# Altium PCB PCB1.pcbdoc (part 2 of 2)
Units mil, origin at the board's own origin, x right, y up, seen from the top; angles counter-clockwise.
Board outline 3622 x 3621.7 mil, 4 copper layers (Top Layer, Inner1, Inner2, Bottom Layer), stack 62.5 mil thick; 107 components, 108 nets, 595 pads, 260 vias.
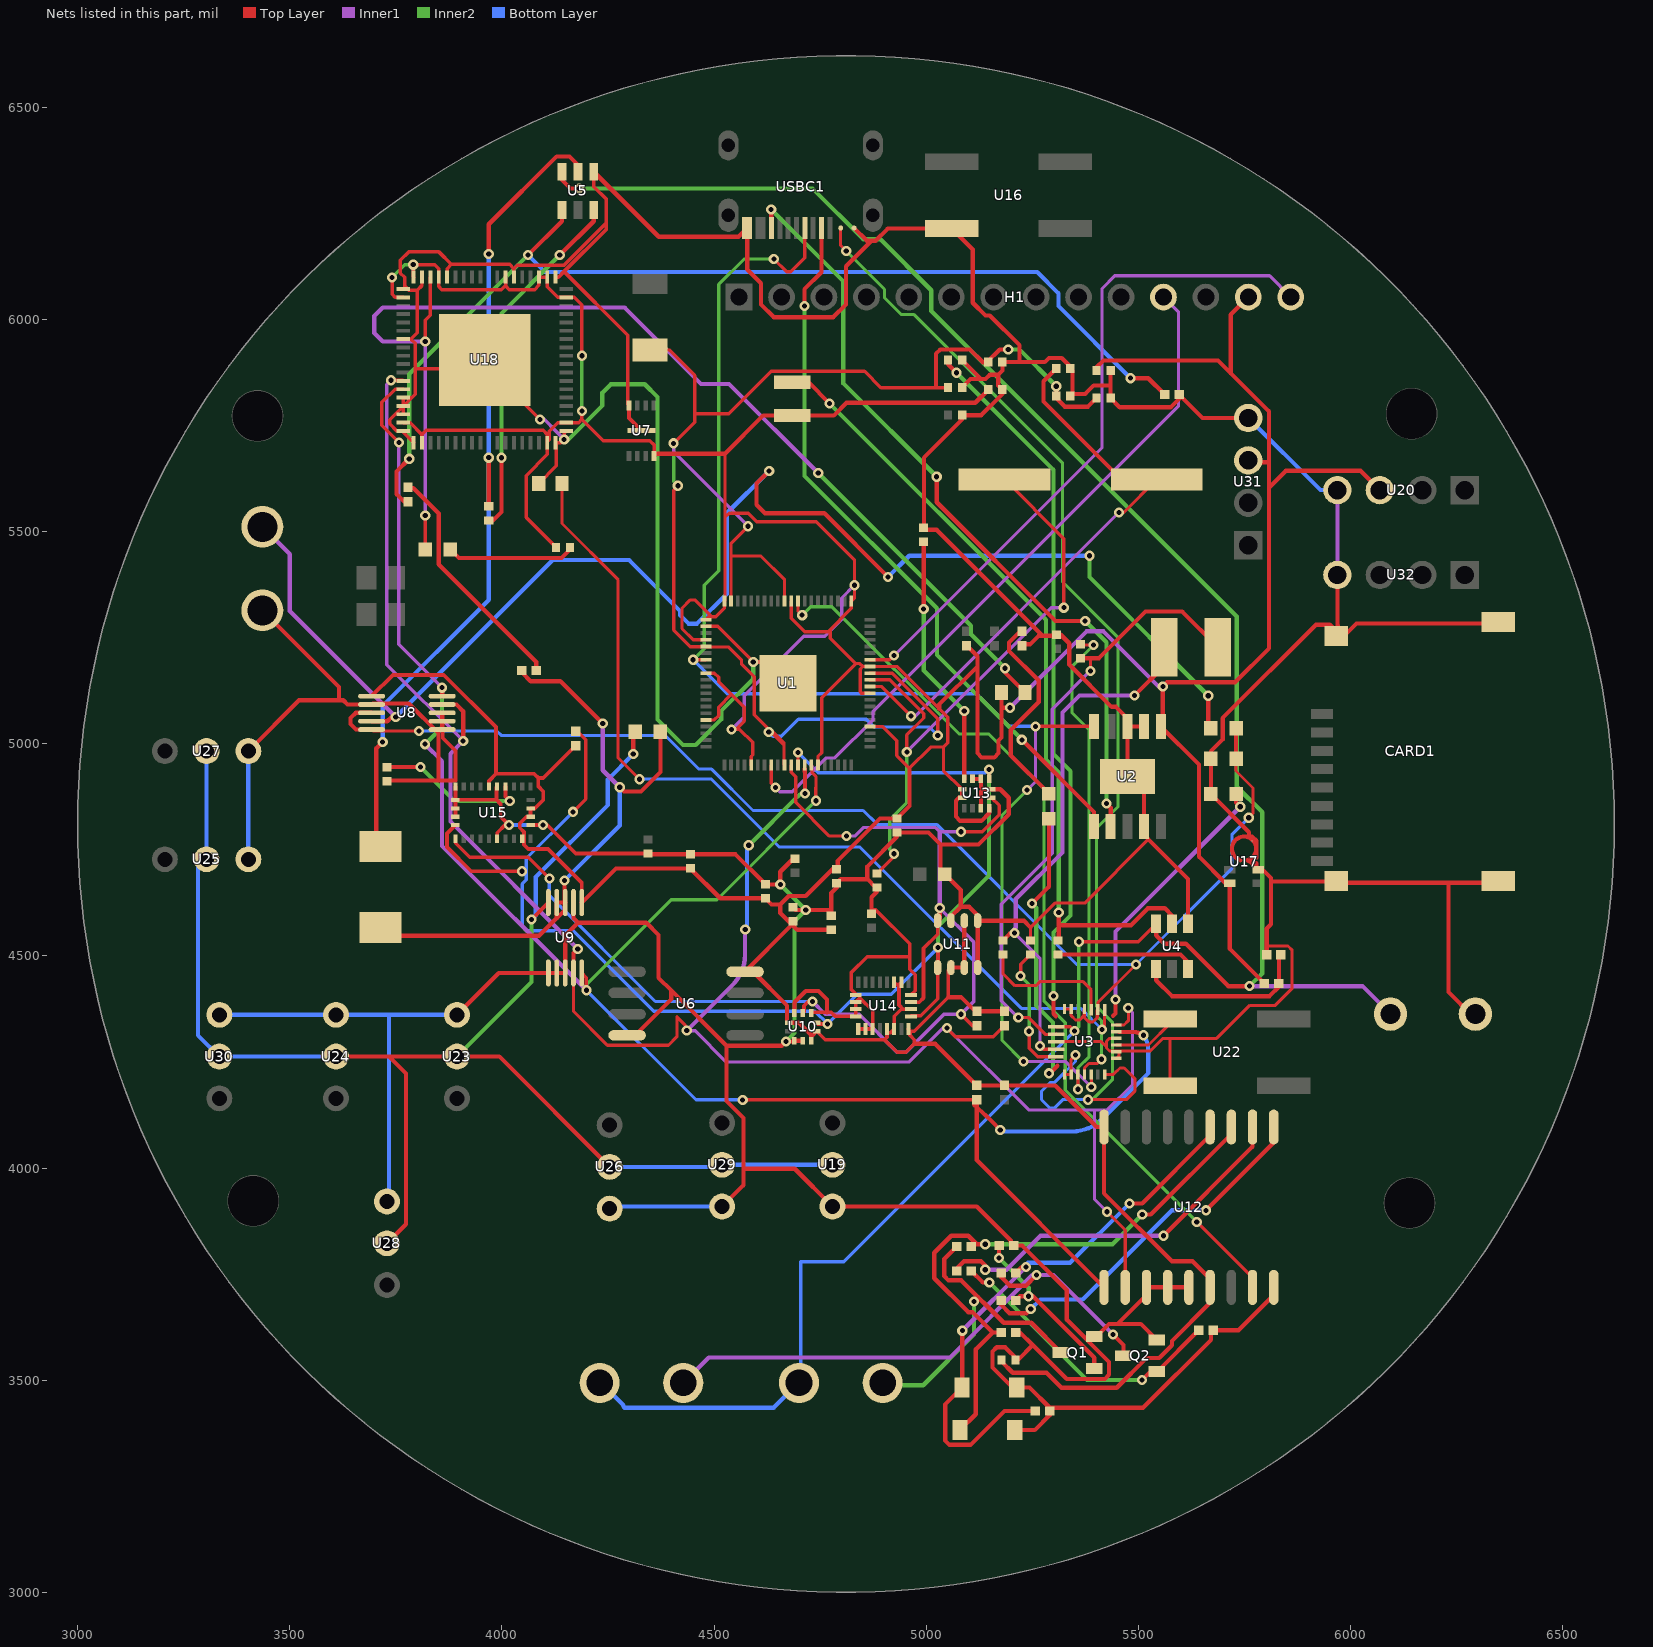
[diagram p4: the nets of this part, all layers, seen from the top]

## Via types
v1: diameter 24, hole 12, Top Layer to Bottom Layer, tented both sides, 260 vias

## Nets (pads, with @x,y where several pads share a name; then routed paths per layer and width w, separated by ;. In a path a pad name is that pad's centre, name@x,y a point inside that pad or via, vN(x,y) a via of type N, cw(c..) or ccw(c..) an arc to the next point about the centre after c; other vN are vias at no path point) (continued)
$1N198: R36.1 U1.11 U10.4 U11.5 U13.11 U14.4 U15.20 | length 2975.9
  Top Layer w7.8: U15.20@3890.5,4776.4 3890.5,4766.4 3924.2,4732.7 4062,4732.7 v1(4112,4682.7) ; U1.11@4682,4949.7 4682,4932.7 4692.4,4922.3 4692.4,4862.3 4772,4782.7 v1(4812,4782.7) ; v1(5082,4792.7) 5132,4792.7 5172,4832.7 5172,4854.7 U13.11@5153.6,4873.1
  Top Layer w8.5: U10.4@4709.1,4365.5 4712,4368.4 4712,4382.7 4722,4392.7 v1(4732,4392.7) ; U14.4@4964.1,4391.4 4964.4,4391.1 4983.7,4391.1 4993.7,4401.1 4993.7,4517.9 5026.9,4551.1 U11.5@5026.9,4583.1 ; v1(5082,4362.7) 5108.9,4335.8 R36.1@5119.3,4335.8
  Top Layer w9.9: U11.5@5026.9,4583.1 5032,4588.2 v1(5032,4612.7)
  Inner1 w7.8: v1(4812,4782.7) 4832,4782.7 4852,4802.7 5022,4802.7 5032,4792.7 v1(5082,4792.7)
  Inner1 w8.5: v1(4732,4392.7) 4762,4362.7 4842,4362.7 4932,4272.7 4952,4272.7 5042,4362.7 v1(5082,4362.7) 5112,4392.7 5112,4532.7 v1(5032,4612.7)
  Inner1 w9.9: v1(5032,4612.7) 5032,4792.7
  Bottom Layer w7.8: v1(4112,4682.7) 4112,4642.7 4362,4392.7 v1(4732,4392.7)
$1N204: C25.1 U15.9 | length 361.4
  Top Layer w8.9: C25.1@3729.1,4944.5 3729.8,4945.2 v1(3808.6,4945.2) ; U15.9@4008.6,4899.5 4008.6,4875.2 v1(4018.6,4865.2)
  Inner2 w8.9: v1(3808.6,4945.2) 3888.6,4865.2 v1(4018.6,4865.2)
$1N209: LED2.2 U3.1 | length 669
  Top Layer w10: v1(5249.1,4623.4) 5289.1,4663.4 LED2.2@5289.1,4823.4 ; v1(5289.1,4223.4) 5291.4,4223.4 5309.3,4241.3
  Inner2 w10: v1(5249.1,4623.4) 5259.1,4613.4 5259.1,4383.4 5299.1,4343.4 5299.1,4233.4 v1(5289.1,4223.4)
$1N210: LED2.1 R8.1 | length 491.1
  Top Layer w10: R8.1@5225.4,5265.5 5222.1,5265.5 5195.4,5238.8 5195.4,5218.8 5265.4,5148.8 5265.4,5098.8 5199.1,5032.5 5199.1,4972.5 LED2.1@5289.1,4882.5
$1N211: C17.1 U3.4 | length 1161.3
  Top Layer w7.1: v1(5357.4,4185.8) U3.4@5357.4,4221.2 ; C17.1@5364.1,5234.5 5366.1,5232.5 v1(5394.1,5232.5)
  Inner2 w7.1: v1(5357.4,4185.8) 5357.4,4235.8 5384.1,4262.5 5384.1,5032.5 5344.1,5072.5 5344.1,5182.5 v1(5394.1,5232.5)
$1N212: C17.2 L4.1 U3.26 | length 1460.1
  Top Layer w7.8: v1(5217.1,4354.8) 5242.1,4354.8 5282.1,4314.8 5305.3,4314.8 U3.26@5306.2,4315.7 ; v1(5387.1,5171.8) 5387.1,5201.8
  Top Layer w10: C17.2@5364.1,5201.4 5364.5,5201.8 5407.1,5201.8 5517.1,5311.8 5603.2,5311.8 L4.1@5687.1,5227.9
  Inner1 w7.8: v1(5217.1,4354.8) 5177.1,4394.8 5177.1,4621.8 5297.1,4741.8 5297.1,5081.8 v1(5387.1,5171.8)
$1N215: U3.12 U22.1 | length 158.8
  Top Layer w7.1: U3.12@5447.9,4290.1 5523.9,4290.1 5575.2,4341.4 U22.1@5575.2,4351.7
$1N219: C18.1 U3.19 | length 324.6
  Top Layer w7.1: C18.1@5180.9,4503.6 5180.9,4458 5208.9,4430.1 5258.9,4430.1 5268.9,4440.1 5368.9,4440.1 5388.9,4420.1 U3.19@5388.9,4373.1
$1N221: R1.1 U3.16 | length 651
  Top Layer w10: 5440.5,4359 5446,4364.5 U3.16@5446,4368.8 v1(5446,4397.4) ; R1.1@5730.2,4881.7 5730.2,4861.7 v1(5740.2,4851.7)
  Inner1 w10: v1(5446,4397.4) 5446,4557.4 v1(5740.2,4851.7)
$1N224: C10.1 U3.25 U4.3 U5.3 U21.1 U33.1 | length 5744.7
  Top Layer w7.8: U3.25@5306.2,4333.4 5339.8,4333.4 v1(5349.8,4323.4) ; v1(5359.8,4533.4) 5499.7,4533.4 U4.3@5541.9,4575.6
  Top Layer w10: U5.3@4141.9,6347.9 4141.9,6328.9 4161.9,6308.9 v1(4181.9,6308.9) ; U4.3@5541.9,4575.6 5541.9,4548.9 5561.9,4528.9 5611.9,4528.9 5711.9,4428.9 v1(5761.9,4428.9)
  Inner1 w10: v1(5761.9,4428.9) 6028.1,4428.9 C10.1@6094.1,4362.9
  Inner2 w7.8: v1(5349.8,4323.4) 5359.8,4333.4 v1(5359.8,4533.4)
  Inner2 w10: v1(4181.9,6308.9) 4731.9,6308.9 4851.9,6188.9 4891.9,6188.9 5011.9,6068.9 5011.9,6020.1 5731.9,5300.1 5731.9,4898.9 5791.9,4838.9 5791.9,4458.9 v1(5761.9,4428.9)
  Bottom Layer w7.8: U21.1@4700.5,3493.9 4700.5,3495.2 4704.6,3499.3 4704.6,3779.3 ; 4706,3779.5 4805.9,3779.5 v1(5349.8,4323.4)
  Bottom Layer w10: U33.1@4244.8,3483.3 4283.7,3444.4 ; 4283.63,3444.33 cw(c4276.7,3437.4) 4286.5,3437.4 ; 4289.2,3435.2 4640.5,3435.2 U21.1@4700.5,3495.2
$1N225: C19.1 U3.29 | length 309.9
  Top Layer w7.8: v1(5222.6,4452.5) 5222.6,4480.2 C19.1@5245.9,4503.6 ; v1(5242.6,4322.5) 5242.6,4282.5 5262.6,4262.5 U3.29@5305.2,4262.5
  Inner2 w7.8: v1(5222.6,4452.5) 5242.6,4432.5 v1(5242.6,4322.5)
$1N229: C18.2 L4.2 U3.28 | length 1262.7
  Top Layer w7.8: v1(5268.3,4288.1) 5276.2,4280.2 U3.28@5306.2,4280.2
  Top Layer w10: C18.2@5180.9,4536.6 5198.3,4554 v1(5208.3,4554) ; v1(5491.1,5114) 5561.1,5184 L4.2@5561.1,5227.9
  Inner1 w7.8: v1(5208.3,4554) 5268.3,4494 v1(5268.3,4288.1)
  Inner1 w10: v1(5208.3,4554) 5208.3,4564 5211.1,4566.8 5211.1,4634 5321.1,4744 5321.1,5074 5361.1,5114 v1(5491.1,5114)
$1N233: U2.7 USBC1.B5 | length 1870.9
  Top Layer w10: v1(4634.7,6259.3) 4634.7,6216 USBC1.B5@4635.2,6215.5 ; v1(5024.7,5629.3) 5024.7,5569.3 5304.7,5289.3 v1(5374.7,5289.3) ; v1(5424.7,4859.3) 5434.7,4849.3 U2.7@5434.7,4804.8
  Inner2 w10: v1(4634.7,6259.3) 4804.7,6089.3 4804.7,5849.3 v1(5024.7,5629.3) ; v1(5374.7,5289.3) 5424.7,5239.3 v1(5424.7,4859.3)
$1N234: U2.6 USBC1.A5 | length 1709.8
  Top Layer w10: v1(4713.3,6031.4) 4713.3,6071.4 4753.3,6111.4 USBC1.A5@4753.3,6215.5 ; v1(5225.4,5009.4) 5395.4,4839.4 U2.6@5395.4,4804.8
  Inner2 w10: v1(4713.3,6031.4) 4713.3,5631.4 5025.4,5319.3 5025.4,5209.4 v1(5225.4,5009.4)
$1N235: U1.67 U2.5 U3.6 USBC1.A6 | length 3331
  Top Layer w7.1: v1(5389,4191) U3.6@5389,4221
  Top Layer w7.8: v1(4450.9,5198.1) U1.67@4480.9,5198.1 ; v1(4640.9,6142.5) 4670.9,6112.5 4680.9,6112.5 4713.9,6145.5 USBC1.A6@4713.9,6215.5 ; v1(5257.9,5041) U2.5@5395.4,5041
  Inner1 w7.1: v1(5229,4251) 5329,4251 v1(5389,4191) ; v1(5237.9,4891) 5257.9,4911 v1(5257.9,5041)
  Inner2 w7.1: v1(5229,4251) 5179,4301 5179,4832.1 v1(5237.9,4891)
  Inner2 w7.8: v1(4450.9,5198.1) 4476.6,5223.7 4476.6,5373.7 4510.9,5408.1 4510.9,6082.5 4570.9,6142.5 v1(4640.9,6142.5)
  Bottom Layer w7.8: v1(4450.9,5198.1) 4530.9,5118.1 5118.4,5118.1 5195.4,5041 v1(5257.9,5041)
$1N241: C21.1 U5.6 | length 839.6
  Top Layer w10: C21.1@3969.1,5526.4 3979.1,5526.4 3999.1,5546.4 v1(3999.1,5674.2) ; v1(4136.5,6151.6) 4216.5,6231.6 U5.6@4216.5,6257.7
  Inner2 w10: v1(3999.1,5674.2) 3999.1,6014.2 v1(4136.5,6151.6)
$1N244: C21.2 L3.1 U5.2 | length 1995.3
  Top Layer w10: L3.1@3714.1,4758.4 3704.1,4768.4 3704.1,4989.3 v1(3719.1,5004.3) ; C21.2@3969.1,5559.5 v1(3969.1,5674.3) ; v1(3969.1,6154.3) 3969.1,6224.3 4129.1,6384.3 4159.1,6384.3 4179.1,6364.3 U5.2@4179.1,6348.2
  Bottom Layer w10: v1(3719.1,5004.3) 3719.1,5089.3 3969.1,5339.3 v1(3969.1,5674.3) 3969.1,5681.8 v1(3969.1,6154.3)
$1N254: H1.11 U1.8 | length 1670.9
  Top Layer w7.8: U1.8@4634.7,4949.7 4634.7,4906.7 v1(4644.7,4896.7)
  Inner1 w7.8: v1(4644.7,4896.7) 4654.7,4886.7 4684.7,4886.7 4764.7,4966.7 4784.7,4966.7 4874.7,5056.7 4874.7,5076.7 5594.7,5796.7 5594.7,6017.3 H1.11@5559.1,6052.9
$1N256: R39.1 U1.14 U3.14 U8.5 U9.5 U12.1 U18.31 | length 4802.5
  Top Layer w7.8: U9.5@4188.5,4459.9 4199.2,4449.1 v1(4199.2,4419.1) ; v1(4567.5,4160.8) R39.1@5119.1,4160.8 ; U1.14@4729.2,4949.7 4730.7,4948.2 4730.7,4932.5 4740.2,4923.1 4740.2,4896.9 4739.5,4896.2 4739.5,4878 4740.2,4877.3 v1(4740.2,4865.9)
  Top Layer w8.1: v1(3757.3,5710.4) 3717.3,5750.4 3717.3,5804.6 3748.4,5835.7 U18.31@3767.3,5835.7
  Top Layer w10: v1(3859.2,5132.3) U8.5@3859.3,5112.3 ; 5112.82,4149.21 cw(c4493.8,3444.6) 5118.94,4143.78 ; 5112.8,4149.3 5116.5,4149.3 ; 5119.01,4143.86 cw(c4493.8,3444.6) v1@5174.2,4090.28 ; R39.1@5119.1,4160.8 5119.1,4143.7 5119.1,4018.9 U12.1@5419.1,3719 ; U3.14@5455.2,4320.7 5490.6,4320.7 cw(c5490.6,4291) v1@5511.6,4312
  Inner1 w8.1: v1(3757.3,5710.4) 3757.3,5234.2 v1(3859.2,5132.3)
  Inner1 w10: v1(3819.2,4999.1) 3859.2,4959.1 3859.2,4759.1 v1(4199.2,4419.1)
  Inner2 w7.8: v1(4199.2,4419.1) 4199.2,4432.7 4399.2,4632.7 4507,4632.7 v1(4740.2,4865.9)
  Inner2 w10: v1(3819.2,4999.1) 3859.2,5039.1 v1(3859.2,5132.3)
  Bottom Layer w7.8: v1(4199.2,4419.1) 4457.5,4160.8 v1(4567.5,4160.8)
  Bottom Layer w10: v1@5174.6,4086.5 5344.2,4086.5 ccw(c5344.2,4186.5) 5414.91,4115.79 5523.5,4224.4 5523.5,4278.9 ; v1@5512.24,4312.94 cw(c5465.9,4278.9) 5523.4,4278.9
  other v1: 5174.5,4089.9 5512.1,4313.1
$1N259: C22.1 U13.4 | length 598.6
  Top Layer w9.9: v1(4994.1,5317.4) C22.1@4994.1,5476.4 ; U13.4@5089.6,4917.4 v1(5089.6,5077.4)
  Inner2 w9.9: v1(4994.1,5317.4) 4994.1,5172.8 v1(5089.6,5077.4)
$1N260: C20.1 U4.6 | length 329.7
  Top Layer w10: C20.1@5311,4503.6 5599.1,4503.6 5616.7,4485.9 U4.6@5616.7,4469.3
$1N262: R2.2 R31.1 U4.4 | length 418.2
  Top Layer w10: U4.4@5541.9,4469.3 5541.9,4442.6 5579.3,4405.3 5809.3,4405.3 5831.2,4427.3 R2.2@5831.2,4435.3 5831.2,4498 R31.1@5836.1,4502.9
$1N267: R5.2 R32.1 U5.4 | length 2519.7
  Top Layer w10: R5.2@3779.1,5570.9 3769.1,5570.9 3751.7,5588.3 3751.7,5641.6 v1(3781.7,5671.6) ; v1(4061.7,6151.6) 4141.7,6231.6 U5.4@4141.7,6257.7 ; v1(5481.7,5861.6) 5523.4,5861.6 R32.1@5562.1,5822.9
  Inner2 w10: v1(3781.7,5671.6) 3781.7,5871.6 v1(4061.7,6151.6)
  Bottom Layer w10: v1(4061.7,6151.6) 4101.7,6111.6 5261.7,6111.6 5311.7,6061.6 5311.7,6031.6 v1(5481.7,5861.6)
$1N277: C20.2 L2.1 U4.2 | length 1909.2
  Top Layer w10: L2.1@4684.1,5852.3 4722.4,5852.3 v1(4772.4,5802.3) ; C20.2@5311,4536.6 5312.4,4538.1 v1(5312.4,4602.3) ; 5312.4,4572.3 5482.4,4572.3 5522.4,4612.3 5562.4,4612.3 5579.3,4595.4 U4.2@5579.3,4575.6
  Inner2 w10: v1(4772.4,5802.3) 5282.4,5292.3 5282.4,4962.3 5312.4,4932.3 v1(5312.4,4602.3)
$1N278: H1.14 U1.34 | length 1606.9
  Top Layer w7.8: U1.34@4867.3,5198.1 4914.3,5198.1 v1(4924.3,5208.1)
  Inner1 w7.8: v1(4924.3,5208.1) 5414.3,5698 5414.3,6072.9 5444.3,6102.9 5809.1,6102.9 H1.14@5859.1,6052.9
$1N293: C2.1 U1.30 X1.2 | length 1369.5
  Top Layer w7.8: U1.30@4867.3,5135.1 4894.3,5135.1 v1(4964.3,5065.1) ; v1(5454.3,5545.1) 5465.5,5545.1 X1.2@5543.4,5622.9
  Top Layer w10: C2.1@5306.5,5884.5 5276.5,5854.5 5276.5,5806.5 5460.1,5622.9 X1.2@5543.4,5622.9
  Inner1 w7.8: v1(4964.3,5065.1) 4974.3,5065.1 v1(5454.3,5545.1)
$1N294: C3.1 U1.31 X1.1 | length 1461
  Top Layer w7.8: U1.31@4867.3,5150.8 4914.3,5150.8 4994.3,5070.8 4994.3,5060.8 4954.3,5020.8 v1(4954.3,4980.8) ; C3.1@4884.1,4694.5 4924.3,4734.7 v1(4924.3,4740.8) ; X1.1@5184.9,5622.9 5324.3,5483.5 v1(5324.3,5320.8)
  Inner1 w7.8: v1(4954.3,4980.8) 5294.3,5320.8 v1(5324.3,5320.8)
  Inner2 w7.8: v1(4924.3,4740.8) 4914.3,4750.8 4914.3,4820.8 4954.3,4860.8 v1(4954.3,4980.8)
$1N305: L3.2 R4.1 R7.2 U9.8 U9.9 | length 1523.4
  Top Layer w10: L3.2@3714.1,4567.5 3734.1,4547.5 4087.8,4547.5 4129.4,4589.1 U9.9@4129.4,4626 U9.8@4149.1,4626 ; R4.1@4047.1,5172.9 4047.1,5168.2 4067.8,5147.5 4137.8,5147.5 v1(4237.8,5047.5) ; 4107.8,4567.5 4147.8,4607.5 v1(4147.8,4677.5) ; v1(4277.8,4897.5) 4287.8,4887.5 4327.8,4887.5 4373.8,4933.5 R7.2@4373.8,5027.9
  Inner1 w10: v1(4237.8,5047.5) 4237.8,4937.5 v1(4277.8,4897.5)
  Bottom Layer w10: v1(4147.8,4677.5) 4277.8,4807.5 v1(4277.8,4897.5)
$1N307: R3.1 R12.1 U3.18 U3.20 U3.22 U3.23 U8.8 U8.10 | length 3149.6
  Top Layer w7.1: U8.10@3693.1,5033.6 3696.6,5030.1 v1(3804.6,5030.1) ; U3.23@5325.9,4374.7 U3.22@5341.6,4374.7 5341.6,4359.3 5351.6,4349.3 5361.6,4349.3 5371.6,4359.3 5371.6,4373.2 U3.20@5373.1,4374.7 5373.1,4354.7 5383.1,4344.7 5393.1,4344.7 5403.1,4354.7 5403.1,4372.2 U3.18@5404.6,4373.7 5404.6,4390.1 v1(5494.6,4480.1) ; R12.1@5730.2,4964.4 5730.2,4935.7 5770.2,4895.7 5770.2,4835.7 v1(5760.2,4825.7)
  Top Layer w10: U8.10@3693.1,5033.6 3656.2,5033.6 3643.3,5046.5 3643.3,5060.6 3655.6,5072.9 U8.8@3693.1,5072.9 ; R12.1@5730.2,4964.4 R3.1@5730.2,5037.1
  Bottom Layer w7.1: v1(3804.6,5030.1) 3988.4,5030.1 3998.4,5020.1 4384.6,5020.1 4464.6,4940.1 4494.6,4940.1 4591.6,4843 4851.6,4843 4884.6,4810.1 5024.6,4810.1 5354.6,4480.1 v1(5494.6,4480.1) 5720.2,4705.7 5720.2,4785.7 v1(5760.2,4825.7)
$1N308: CN1.1 R3.2 U8.9 | length 3494.1
  Top Layer w10: U8.9@3693.1,5053.2 3730,5053.2 3740,5063.2 v1(3750,5063.2) ; v1(4630,5643.2) 4600,5613.2 4600,5563.2 4620,5543.2 4760,5543.2 v1(4910,5393.2) ; v1(5664.8,5113.2) 5664.8,5043.2 R3.2@5670.9,5037.1
  Inner1 w10: CN1.1@3435.6,5511.4 3500,5446.9 3500,5313.2 v1(3750,5063.2)
  Inner2 w10: v1(5384.8,5443.2) 5384.8,5393.2 v1(5664.8,5113.2)
  Bottom Layer w10: v1(3750,5063.2) 4120,5433.2 4300,5433.2 4420,5313.2 4420,5303.2 4440,5283.2 4460,5283.2 4530,5353.2 4530,5543.2 v1(4630,5643.2) ; v1(4910,5393.2) 4960,5443.2 v1(5384.8,5443.2)
$1N310: R4.2 R5.1 | length 563
  Top Layer w10: R5.1@3779.1,5605 3781.1,5602.9 3791.1,5602.9 3851.1,5542.9 3851.1,5422.9 4081.1,5192.9 R4.2@4081.1,5172.9
$1N315: R7.1 U9.10 U19.2 U23.2 U24.2 U25.2 U26.2 U27.2 U28.2 U29.2 U30.2 | length 3774.6
  Top Layer w10: U24.2@3609.1,4262.9 U23.2@3894.1,4262.9 3994.1,4262.9 U26.2@4254.1,4002.9 ; U28.2@3729.1,3822.9 3774.1,3867.9 3774.1,4222.9 3734.1,4262.9 ; v1(4069.7,4586) U9.10@4109.7,4626 ; v1(4309.7,4976) 4309.7,5023.2 R7.1@4314.4,5027.9
  Inner2 w10: U23.2@3894.1,4262.9 4069.7,4438.6 v1(4069.7,4586)
  Bottom Layer w10: U27.2@3304.1,4982.9 U25.2@3304.1,4727.9 3284.1,4707.9 3284.1,4312.9 U30.2@3334.1,4262.9 U24.2@3609.1,4262.9 ; v1(4069.7,4586) 4079.7,4596 4079.7,4686 4249.7,4856 4249.7,4916 v1(4309.7,4976) ; U26.2@4254.1,4002.9 4514.1,4002.9 U29.2@4519.1,4007.9 U19.2@4779.1,4007.9
$1N316: C6.1 U3.24 | length 1685.2
  Top Layer w10: C6.1@5051.5,5904.5 5051.5,5894.5 v1(5071.5,5874.5) ; v1(5300.3,4405.6) U3.24@5300.3,4367.8 5300.3,4363.8 5306.2,4357.9
  Inner2 w10: v1(5071.5,5874.5) 5300.3,5645.6 5300.3,4975.6 5340.3,4935.6 5340.3,4595.6 5300.3,4555.6 v1(5300.3,4405.6)
$1N322: C8.2 R10.1 U18.16 | length 2750.3
  Top Layer w8.1: R10.1@3819.4,5457.9 v1(3819.4,5538.1) ; v1(3819.4,5948.1) 3819.4,5998.1 3831.5,6010.2 U18.16@3831.5,6100
  Top Layer w10: v1(5185.5,5178.1) 5185.5,5168.1 C8.2@5232.7,5121
  Inner1 w8.1: v1(3819.4,5538.1) v1(3819.4,5948.1)
  Inner1 w10: v1(3819.4,5948.1) 3719.4,5948.1 3699.4,5968.1 3699.4,6008.1 3719.4,6028.1 4289.4,6028.1 4469.4,5848.1 4535.5,5848.1 v1(4745.5,5638.1)
  Inner2 w10: v1(4745.5,5638.1) 5105.5,5278.1 5105.5,5258.1 v1(5185.5,5178.1)
$1N323: C9.2 R10.2 | length 303.4
  Top Layer w10: R10.2@3878.8,5457.9 3898.8,5437.9 4140.6,5437.9 4160.6,5457.9 C9.2@4160.6,5462.9
$1N330: C7.1 U3.5 U3.17 | length 2355.8
  Top Layer w7.1: C7.1@4141.7,5612.9 4141.7,5519 4274.2,5386.5 4274.2,4966.5 v1(4324.2,4916.5) ; U3.5@5373.1,4221.2 5373.1,4236.5 5383.1,4246.5 5403.1,4246.5 v1(5413.1,4256.5) ; v1(5414.2,4326.5) 5420.4,4332.7 U3.17@5420.4,4372.7
  Inner2 w7.1: v1(5413.1,4256.5) 5413.1,4346.5 5404.2,4355.5 5404.2,4356 5404.7,4356 5414.2,4346.5 v1(5414.2,4326.5)
  Bottom Layer w7.1: v1(4324.2,4916.5) 4494.2,4916.5 4654.2,4756.5 4844.2,4756.5 5224.2,4376.5 5364.2,4376.5 v1(5414.2,4326.5)
$1N333: R37.1 U1.12 U10.2 U11.4 U13.1 U14.2 U15.19 | length 3188.6
  Top Layer w7.8: v1(4167.7,4839.7) 4197.7,4869.7 4197.7,5009.7 4177.5,5030 R37.1@4174.1,5030 ; U1.12@4697.7,4949.7 v1(4697.7,4979.7) ; v1(5147.7,4939.7) 5147.7,4918.3 U13.1@5148.6,4917.4
  Top Layer w8.5: U10.2@4741.9,4342.6 4744.7,4339.7 v1(4767.7,4339.7) ; U14.2@4964.1,4357.5 4965.4,4358.9 4986.9,4358.9 5026.9,4398.9 U11.4@5026.9,4478.9
  Top Layer w8.9: U15.19@3890.5,4808.4 3870.5,4788.4 3870.5,4756.9 3927.7,4699.7 v1(4047.7,4699.7)
  Top Layer w9.9: U11.4@5026.9,4472.8 5026.9,4478.9 5027.7,4479.7 v1(5027.7,4519.7)
  Inner2 w9.9: v1(5027.7,4519.7) 5027.7,4569.7 5147.7,4689.7 v1(5147.7,4939.7)
  Bottom Layer w7.8: v1(4167.7,4839.7) 4057.7,4729.7 4057.7,4679.7 4047.7,4669.7 4047.7,4569.7 4057.7,4559.7 4167.7,4559.7 4357.7,4369.7 4737.7,4369.7 v1(4767.7,4339.7) ; v1(4697.7,4979.7) 4745.8,4931.7 5139.7,4931.7 v1(5147.7,4939.7)
  Bottom Layer w8.5: v1(4767.7,4339.7) 4777.7,4349.7 4837.7,4409.7 4917.7,4409.7 v1(5027.7,4519.7)
  Bottom Layer w8.9: v1(4047.7,4699.7) 4057.7,4689.7
$1N335: C1.2 C2.2 C3.2 C4.2 C5.2 C6.2 C7.2 C10.2 C11.2 C12.2 C13.2 C14.2 C16.2 C19.2 C22.2 C23.2 C24.2 C25.2 C26.2 C27.2 C28.2 C29.2 C30.2 C31.2 C32.2 C33.2 CARD1.10 CARD1.11 CARD1.12 CARD1.13 CN1.2 D1.2 D2.2 LED1.1 Q1.2 Q2.2 R1.2 R8.2 R12.2 R14.2 R15.2 R19.2 R20.2 R31.2 R32.2 U1.62 U1.81 U2.2 U2.3 U2.9 U2.11 U3.10 U3.11 U3.13 U3.27 U4.1 U5.1 U6.4 U7.4 U7.9 U8.1 U8.2 U8.3 U8.7 U9.1 U9.2 U9.3 U9.7 U10.3 U10.5 U10.8 U10.9 U11.1 U11.6 U11.8 U12.3 U12.4 U12.5 U12.9 U13.2 U13.3 U13.9 U13.12 U14.5 U14.14 U14.15 U14.16 U14.17 U14.18 U14.19 U14.20 U15.2 U15.10 U15.15 U15.16 U15.17 U15.18 U15.25 U16.3 U17.4 U17.5 U18.1 U18.6 U18.14 U18.17 U18.19 U18.25 U18.32 U18.33 U18.34 U18.36 U18.37 U18.54 U18.55 U18.73 U19.3 U20.4 U22.3 U23.3 U24.3 U25.3 U26.3 U27.3 U28.3 U29.3 U30.3 U31.4 U32.4 USBC1.A1B12 USBC1.B1A12 | length 24588.7
  Top Layer w7.1: U3.27@5306.2,4297.9 5412.6,4297.9 5424.7,4285.8 ; U3.10@5447.9,4258.6 5454.7,4265.4 U3.11@5454.7,4275.8 ; U3.13@5447.9,4305.8 5431.8,4305.8 5424.7,4298.7 5424.7,4285.8 ; U22.3@5575.2,4194.2 5574.7,4194.7 5574.7,4305.8 ; 5802.6,4523.6 5852.6,4523.6 5862.6,4513.6 5862.6,4423.6 5822.6,4383.6 5762.6,4383.6 5684.7,4305.8 5574.7,4305.8 ; 5424.7,4285.8 5424.7,4282.9 5431.8,4275.8 U3.11@5454.7,4275.8 ; U3.11@5454.7,4275.8 5528.1,4275.8 5558.1,4305.8 5574.7,4305.8
  Top Layer w7.8: U1.62@4480.9,5276.8 4508.6,5276.8 v1(4592.5,5192.9) ; C19.2@5245.9,4536.6 5245.9,4567.3 5303.5,4624.8 5373.5,4624.8 5523.5,4774.8
  Top Layer w8.1: U18.34@3767.3,5776.6 U18.33@3767.3,5795.5 ; U18.33@3767.3,5796.3 U18.32@3767.3,5816 3787.8,5816 ; U18.25@3767.3,5953.8 3785.6,5953.8 ; U18.19@3767.3,6071.9 3770.9,6075.4 3770.9,6079.1 ; U18.37@3792.1,5709.1 3767.3,5733.9 U18.36@3767.3,5737.2 3752.1,5737.2 3735.6,5753.8 3735.6,5763.8 U18.33@3767.3,5795.5 ; U18.17@3811.8,6100 3811.8,6080 3800.9,6069.1 ; U18.14@3870.9,6100 3870.9,6120 3880.9,6130 ; U18.6@4028.4,6100 4028.4,6120 ; C7.2@4086.5,5612.9 4128.6,5655 U18.54@4128.6,5709.1 ; v1(4089.5,5764.5) 3959.5,5894.5 U18.73@3959.5,5904.5 3938.7,5883.8 3795.6,5883.8 ; U18.54@4126.8,5709.1 U18.54@4128.6,5709.1 ; U18.1@4126.8,6100 4133.5,6100 4146.5,6113 ; U18.55@4151.6,5737.2 4146.8,5732.4 v1(4146.8,5717.2) 4138.6,5709.1 U18.54@4128.6,5709.1 ; U5.1@4216.5,6348.2 4216.5,6313 4246.5,6283 4246.5,6228.2 ; U7.4@4299.6,5797.3 4296.5,5800.3 4296.5,5963 4146.5,6113 ; U18.33@3767.3,5795.5 3787.8,5816 ; 3770.9,6079.1 3770.9,6099.1 3760.9,6109.1 3760.9,6139.1 3780.9,6159.1 3851.8,6159.1 3880.9,6130 ; 3770.9,6079.1 3780.9,6069.1 3800.9,6069.1 ; 3785.6,5953.8 3800.9,5969.1 3800.9,6069.1 ; 3785.6,5953.8 3795.6,5943.8 3795.6,5883.8 ; 3787.8,5816 3795.6,5823.8 3795.6,5883.8 ; 3880.9,6130 4018.4,6130 4028.4,6120 ; 4028.4,6120 4036.5,6128.2 4146.5,6128.2 4246.5,6228.2 ; 4146.5,6113 4246.5,6213 4246.5,6228.2
  Top Layer w8.5: U10.3@4728.8,4365.5 4730.8,4367.5 4766.1,4367.5 4776.1,4367.5 4786.1,4357.5 U14.17@4834.1,4357.5 U14.16@4834.1,4374.5 U14.15@4834.1,4391.4 4843.7,4401 4873.7,4371 U14.20@4873.7,4327.8 U14.19@4856.8,4327.8 U14.18@4839.9,4327.8 ; U14.14@4834.1,4408.3 4833.7,4408.7 4833.7,4411 4823.7,4421 4823.7,4461 4861.2,4498.5 4961.2,4498.5 ; C23.2@4871.2,4608.5 4881.2,4608.5 4961.2,4528.5 4961.2,4498.5 ; U14.5@4964.1,4408.3 4974.1,4418.3 4974.1,4455.6 4961.2,4468.5 4961.2,4498.5
  Top Layer w8.9: C25.2@3729.1,4911.4 3731.5,4913.7 3850.5,4913.7 3890.5,4913.7 3890.5,4983.7 3860.5,5013.7 3860.5,5032.3 U8.1@3859.3,5033.6 ; U15.18@3890.5,4828.1 U15.17@3890.5,4847.8 U15.16@3890.5,4867.5 ; U15.15@3890.5,4899.5 U15.16@3890.5,4867.5 ; U15.25@3988.9,4776.4 3988.9,4790.3 4007.1,4808.4 v1(4017.1,4808.4) 3997.1,4828.4 3997.1,4858.4 3987.1,4868.4 ; U15.10@3988.9,4899.5 3987.1,4897.6 3987.1,4868.4 ; U15.2@4067.7,4808.4 4107.1,4808.4 4174.1,4741.4 C5.2@4344.1,4741.4 ; U15.16@3890.5,4867.5 3891.5,4868.4 3987.1,4868.4
  Top Layer w9.9: U7.4@4299.6,5797.3 4299.6,5767.5 U7.9@4329.1,5737.9 ; U29.3@4519.1,3909.5 4569.4,3959.8 4569.4,3998.4 4569.4,4118.4 4529.4,4158.4 4529.4,4288.4 ; v1(4669.4,4298.4) 4687.5,4298.4 U10.8@4689.4,4300.4 U10.9@4709.1,4300.4 ; U10.5@4689.4,4365.5 4689.4,4390.9 4716.1,4417.5 4746.1,4417.5 4766.1,4397.5 4766.1,4367.5 ; 5033.6,4762.9 5123.6,4762.9 5194.5,4833.8 5194.5,4872.9 5174.5,4892.9 U13.12@5154.5,4892.9 ; U13.3@5109.3,4917.4 U13.2@5128.9,4917.4 5128.9,4898.5 5134.5,4892.9 ; U13.9@5128.9,4848.5 5128.9,4887.4 5134.5,4892.9 ; U13.12@5153.6,4892.8 U13.12@5154.5,4892.9 ; 5134.5,4892.9 U13.12@5154.5,4892.9
  Top Layer w10: U27.3@3402.5,4982.9 3522.2,5102.6 3616.2,5102.6 ; CN1.2@3435.6,5314.5 3616.2,5133.8 3616.2,5102.6 ; 3850.5,4913.7 3850.5,5025.2 3780.5,5095.2 3695.7,5095.2 U8.7@3693.1,5092.6 3636.2,5092.6 3626.2,5102.6 3616.2,5102.6 ; U8.1@3859.3,5033.6 3859.3,5053.2 U8.3@3859.3,5072.9 ; U23.3@3894.1,4361.4 3992.6,4459.9 U9.1@4109.7,4459.9 U9.2@4129.4,4459.9 U9.3@4149.1,4459.9 4149.1,4548.1 4179.4,4578.4 ; U9.7@4168.8,4626 4168.8,4589.1 4179.4,4578.4 ; U5.1@4216.5,6348.2 4369.7,6194.9 4557.5,6194.9 USBC1.B1A12@4578.1,6215.5 4578.1,6118.3 4610.9,6085.5 4610.9,6035.5 4640.9,6005.5 4780.9,6005.5 4810.9,6035.5 4810.9,6125.5 4870.9,6185.5 ; U6.4@4295.1,4312.9 4313.9,4312.9 4399.4,4398.4 4399.4,4418.4 ; C5.2@4344.1,4741.4 4346,4739.5 C29.2@4444.1,4739.5 4550.7,4739.5 C27.2@4621.2,4669 4621.8,4668.4 v1(4656.2,4668.4) 4656.2,4698.4 4686.8,4729 C24.2@4691.2,4729 ; 4569.4,3998.4 4690.2,3998.4 U19.3@4779.1,3909.5 5119.1,3909.5 5199.1,3829.5 5199.1,3825 R14.2@5206.1,3817.9 5226.1,3817.9 5331.1,3712.9 5331.1,3642.9 5431.1,3542.9 5431.1,3512.9 5421.1,3502.9 5331.1,3502.9 5251.1,3582.9 ; v1(4592.5,5192.9) 4624.1,5192.9 U1.81@4674.1,5142.9 ; v1(4669.4,4298.4) 4659.4,4288.4 4529.4,4288.4 4399.4,4418.4 ; C32.2@4686.1,4614.6 4692.2,4608.4 v1(4716.2,4608.4) 4776.2,4608.4 ; C26.2@4776.2,4594.6 4776.2,4608.4 ; USBC1.A1B12@4830.1,6215.5 4860.1,6185.5 4870.9,6185.5 ; C23.2@4871.2,4599.6 4871.2,4608.5 4871.2,4638.5 4884.1,4651.4 C3.2@4884.1,4661.4 4880.8,4661.4 4861.3,4681 ; C22.2@4994.1,5509.5 C22.2@4994.6,5504.4 ; U11.6@5058.4,4583.1 5058.4,4592.8 5081.3,4615.8 ; C1.2@5084.6,5774.4 5084.6,5764.4 4994.6,5674.4 C22.2@4994.6,5504.4 ; C14.2@5084.6,5839.4 5104.7,5859.5 5129.5,5859.5 ; C6.2@5084.6,5904.5 5129.5,5859.5 ; C1.2@5084.7,5774.5 5129.6,5774.5 5179.6,5824.5 C31.2@5179.6,5834.5 5169.6,5844.5 5169.6,5869.5 ; U11.1@5121.3,4472.8 U11.8@5121.3,4583.1 ; D2.2@5208.5,3382.9 5256.1,3382.9 5291.1,3417.9 R19.2@5291.1,3427.9 R19.2@5291.1,3435.3 ; C16.2@5210.6,3547.9 C16.2@5216.1,3547.9 ; R15.2@5211.1,3612.9 5221.1,3612.9 5251.1,3582.9 ; R8.2@5225.4,5231.4 5228.5,5234.4 5244.6,5234.4 5264.6,5254.4 5274.6,5254.4 ; 5245.9,4567.3 5230.2,4583.1 U11.8@5121.3,4583.1 ; C13.2@5339.6,5819.5 C13.2@5344.6,5824.6 ; Q1.2@5396.1,3602.9 5401.1,3602.9 5431.1,3632.9 5451.1,3632.9 ; C28.2@5434.6,5879.6 5434.6,5844.6 ; U2.9@5513.5,4804.8 5513.5,4883.6 U2.11@5474.1,4922.9 U2.3@5474.1,5041 ; U2.2@5513.5,5041 U2.3@5474.1,5041 ; 5523.5,4774.8 5616.7,4681.5 U4.1@5616.7,4575.6 ; Q2.2@5543.5,3595.3 5505.9,3632.9 5451.1,3632.9 ; U12.5@5619.1,3719 U12.4@5569.1,3719 U12.3@5519.1,3719 5519.1,3700.9 5451.1,3632.9 ; 5739.88,4725.83 cw(c5749.1,4752.9) 5741.51,4780.47 cw(c5749.1,4752.9) 5764.04,4777.29 cw(c5749.1,4752.9) 5777.7,4752.9 ; 5756.69,4725.31 cw(c5750.7,4703.1) 5767.82,4718.46 ; 5756.69,4725.33 ccw(c5749.1,4752.9) 5777.7,4752.9 ; U31.4@5759.1,5767.9 5651.1,5767.9 R32.2@5596.1,5822.9 5596.1,5812.9 5576.1,5792.9 5456.2,5792.9 C12.2@5434.6,5814.6 5434.6,5844.6 ; 5764.1,4777.3 5760.9,4781.7 ; 5767.9,4718.5 5774.9,4718.5 ; 5777.7,4718.5 5777.7,4708.5 U17.4@5782.6,4703.6 5792.6,4703.6 5812.6,4683.6 5812.6,4675.5 ; 5777.7,4731.6 5777.7,4752.9 ; R31.2@5802.1,4502.9 5802.6,4503.4 5802.6,4523.6 5802.6,4564.9 5812.6,4574.9 5812.6,4675.5 ; U12.9@5819.1,3719 5816.1,3716 5816.1,3697.9 5736.1,3617.9 R20.2@5676.1,3617.9 5671.1,3612.9 5671.1,3595.3 5511.1,3435.3 R19.2@5291.1,3435.3 ; 5969.1,5329.8 U32.4@5969.1,5397.9 ; 5969.3,5327.8 5969.3,5284.2 ccw(c6004.3,5284.2) CARD1.13@5979.55,5259.45 ; CARD1.13@5975.8,5255.7 5951.1,5280.4 5918.6,5280.4 5698.6,5060.4 5698.6,5010.4 5670.9,4982.7 R12.2@5670.9,4964.4 R1.2@5670.9,4881.7 5760.9,4791.7 5760.9,4781.7 ; CARD1.10@5979.9,4673.6 5981.1,4672.4 6231.1,4672.4 ; CARD1.13@5984.9,5254.1 6014.2,5283.4 CARD1.12@6363.1,5283.4 ; CARD1.10@5987.4,4675.5 5812.6,4675.5 ; C10.2@6288,4358 6231.1,4414.8 6231.1,4672.4 ; C10.2@6294.1,4362.9 C10.2@6298.6,4367.4 ; CARD1.11@6363.1,4672.4 6231.1,4672.4 ; 4179.4,4578.4 4340.5,4578.4 4369.4,4549.5 4369.4,4448.4 4399.4,4418.4 ; 4776.2,4608.4 4776.2,4648.4 4789.1,4661.4 C33.2@4789.1,4671.4 4798.7,4681 4861.3,4681 ; 4861.3,4681 4861.3,4711 4931.3,4781 C30.2@4931.3,4791 5005.6,4791 5033.6,4762.9 5033.6,4702.9 LED1.1@5043.6,4692.9 5081.3,4655.2 5081.3,4615.8 ; 4870.9,6185.5 4880.9,6185.5 4909.6,6214.2 U16.3@5060.2,6214.2 5109.6,6164.9 5109.6,6039.5 5139.6,6009.5 5149.6,6009.5 5219.6,5939.5 5219.6,5899.5 ; C22.2@4994.6,5504.4 5024.6,5504.4 5274.6,5254.4 ; 5081.3,4615.8 5101.3,4615.8 5121.3,4595.8 U11.8@5121.3,4583.1 ; 5129.5,5859.5 5139.6,5859.5 5149.6,5869.5 5169.6,5869.5 ; 5169.6,5869.5 5179.6,5879.5 C11.2@5179.6,5899.5 5219.6,5899.5 ; C16.2@5216.1,3547.9 5251.1,3582.9 ; C16.2@5216.1,3547.9 5186.1,3577.9 5166.1,3577.9 5156.1,3567.9 5156.1,3530.3 5203.5,3482.9 D1.2@5213.5,3482.9 5243.5,3482.9 R19.2@5291.1,3435.3 ; 5219.6,5899.5 5279.6,5899.5 5289.6,5909.5 5319.6,5909.5 5339.6,5889.5 C2.2@5339.6,5884.5 5344.6,5879.5 C13.2@5344.6,5824.6 ; 5274.6,5254.4 5304.4,5254.4 C4.2@5307,5257.1 5317,5257.1 5337,5237.1 5337,5187.1 5437,5087.1 5447,5087.1 5474.1,5060 U2.3@5474.1,5041 ; C13.2@5344.6,5824.6 5374.6,5824.6 5394.6,5844.6 5434.6,5844.6 ; 5760.9,4781.7 5767.7,4781.7 5777.7,4771.7 5777.7,4752.9
  Inner1 w8.1: v1(4089.5,5764.5) 4099.5,5764.5 4126.8,5737.2 v1(4146.8,5717.2)
  Inner1 w10: U32.4@5969.1,5397.9 U20.4@5969.1,5597.9
  Inner2 w9.9: v1(4669.4,4298.4) 4689.4,4318.4 4689.4,4581.7 v1(4716.2,4608.4)
  Inner2 w10: v1(4146.8,5717.2) 4156.8,5717.2 4236.8,5797.2 4236.8,5827.2 4256.8,5847.2 4336.8,5847.2 4366.8,5817.2 4366.8,5057.2 4426.8,4997.2 4456.8,4997.2 4516.8,5057.2 4516.8,5077.2 4592.5,5152.9 v1(4592.5,5192.9) ; v1(4656.2,4668.4) v1(4716.2,4608.4)
  Bottom Layer w8.9: v1(4017.1,4808.4) v1(4097.1,4808.4)
  Bottom Layer w10: U30.3@3334.1,4361.4 U24.3@3609.1,4361.4 3734.1,4361.4 ; U25.3@3402.5,4727.9 U27.3@3402.5,4982.9 ; U28.3@3729.1,3921.4 3734.1,3926.4 3734.1,4361.4 ; U23.3@3894.1,4361.4 3734.1,4361.4 ; U26.3@4254.1,3904.5 4259.1,3909.5 U29.3@4519.1,3909.5 ; U31.4@5759.1,5767.9 5929.1,5597.9 U20.4@5969.1,5597.9
$1N338: C8.1 C9.1 C16.1 C26.1 C27.1 C28.1 C29.1 C30.1 C31.1 C32.1 C33.1 H1.13 L2.2 R2.1 R6.2 R17.2 R36.2 R37.2 R38.2 R39.2 U1.5 U1.15 U1.24 U1.29 U1.33 U1.41 U1.50 U1.60 U1.61 U1.64 U1.69 U1.76 U2.1 U6.8 U7.8 U8.6 U9.6 U10.1 U10.6 U10.10 U11.2 U11.3 U11.7 U12.6 U12.18 U13.5 U13.6 U13.10 U14.1 U14.3 U14.7 U14.8 U14.22 U14.23 U15.3 U15.4 U15.11 U15.28 U17.1 U18.2 U18.3 U18.7 U18.15 U18.18 U18.20 U18.35 U18.38 U18.53 U18.56 U18.71 U20.3 U31.3 | length 15736.2
  Top Layer w7.8: U1.76@4480.9,5056.3 4500.7,5056.3 4510.9,5066.5 4510.9,5086.5 4540.9,5116.5 ; U1.69@4480.9,5166.5 4500.9,5166.5 4510.9,5156.5 4510.9,5146.5 4570.9,5086.5 4570.9,5053.6 v1@4550.9,5033.6 ; U1.64@4480.9,5245.3 4450.9,5245.3 4424.5,5271.7 4424.5,5319.1 4444.5,5339.1 4454.5,5339.1 4494.5,5299.1 ; U1.61@4480.9,5292.5 4487.5,5299.1 4504.5,5299.1 4524.5,5319.1 U1.60@4524.5,5336.1 4525.8,5337.5 4525.8,5683.6 ; 4525.8,5533.6 4535.8,5543.6 4580.9,5543.6 4600.9,5523.6 4740.9,5523.6 4830.9,5433.6 v1(4830.9,5373.6) 4830.9,5343.3 U1.41@4823.7,5336.1 4823.7,5319.1 4769,5264.4 4713.7,5264.4 4682,5296.1 U1.50@4682,5336.1 ; v1(4540.9,5033.6) v1@4550.9,5033.6 ; U1.5@4587.5,4949.7 4587.5,4970.2 4590.9,4973.6 4590.9,5003.6 4560.9,5033.6 v1@4550.9,5033.6 ; U1.15@4745,4949.7 4745,4970.4 4753.7,4979.1 4753.7,5109.1 4833.7,5189.1 ; 4773.7,5269.1 4773.7,5249.1 4833.7,5189.1 ; U1.33@4860.6,5182.3 4930.6,5182.3 5050.6,5062.3 5050.6,5002.3 5040.6,4992.3 ; U1.24@4867.3,5040.6 4897.3,5040.6 4930.6,5007.3 4930.6,4972.3 4960.6,4942.3 5010.6,4992.3 5040.6,4992.3 ; U1.29@4867.3,5119.3 4847.3,5119.3 4844.3,5122.3 4844.3,5176.1 4850.6,5182.3 ; U1.33@4867.3,5182.3 4850.6,5182.3 ; U13.5@5084.7,4892.8 5040.6,4936.9 5040.6,4992.3 ; 4833.7,5189.1 4843.7,5189.1 4850.6,5182.3
  Top Layer w8.1: v1(3741.2,6099.1) 3741.2,6059.1 3748.1,6052.2 U18.20@3767.3,6052.2 ; U18.35@3767.3,5756.9 3783.6,5756.9 3811.6,5728.9 ; v1(3791.2,6129.1) v1@3791.2,6119.1 ; U18.18@3792.1,6100 3791.2,6101 v1@3791.2,6119.1 ; U18.38@3811.6,5709.3 3811.6,5728.9 ; C9.1@4127.6,5462.9 4057.1,5533.4 4057.1,5632.2 4107.1,5682.2 U18.53@4107.1,5712.2 ; v1(4188.6,5784.5) 4188.6,5764.5 ; v1(4188.6,5914.5) 4188.6,6034.5 4170.9,6052.2 U18.71@4151.6,6052.2 4131.8,6052.2 4107.1,6076.9 U18.2@4107.1,6100 U18.3@4087.4,6100 4087.4,6080.2 4077.4,6070.2 4017.4,6070.2 4008.7,6078.9 U18.7@4008.7,6100 4008.7,6080.2 3998.7,6070.2 3858.7,6070.2 3851.2,6077.7 U18.15@3851.2,6100 3851.2,6119.8 3842,6129.1 3801.2,6129.1 v1@3791.2,6119.1 ; U7.8@4358.6,5678.6 4358.6,5704.5 4348.6,5714.5 4238.6,5714.5 4188.6,5764.5 ; 3811.6,5728.9 3821.6,5738.9 4097.1,5738.9 4107.1,5728.9 U18.53@4107.1,5709.1 U18.53@4107.1,5712.2 ; U18.53@4107.1,5712.2 4111.8,5716.9 4111.8,5736.9 4131.8,5756.9 U18.56@4151.6,5756.9 4181.1,5756.9 4188.6,5764.5
  Top Layer w8.5: U10.1@4741.9,4322.9 4761.9,4302.9 4901.9,4302.9 ; U14.22@4907.6,4318.6 4915.3,4318.6 U14.23@4924.5,4327.8 4924.5,4357.8 4941.1,4374.5 U14.3@4964.1,4374.5 4946,4374.5 4936,4384.5 4936,4432.6 ; U14.22@4907.6,4327.8 4907.6,4308.6 4901.9,4302.9 ; U14.8@4924.5,4438.1 4929.9,4432.6 4936,4432.6 ; U14.7@4941.4,4438.1 4936,4432.6 ; U14.1@4958.4,4327.8 U14.1@4961.9,4322.9 ; U11.3@5058.4,4472.8 5051.9,4466.3 5051.9,4402.9 4971.9,4322.9 U14.1@4961.9,4322.9 ; 4901.9,4302.9 4931.9,4272.9 4951.9,4272.9 4971.9,4292.9 4971.9,4302.9 4961.9,4312.9 U14.1@4961.9,4322.9
  Top Layer w8.9: U8.6@3693.1,5112.3 3743.1,5162.3 3863.2,5162.3 3986,5039.5 3986,4929.5 ; U15.11@3969.3,4899.5 3969.3,4912.7 3986,4929.5 ; U15.28@4048,4776.4 U15.28@4052.1,4772.3 ; R37.2@4174.1,4995.9 4097.7,4919.5 4086,4919.5 ; U9.6@4188.5,4626 4188.5,4672.3 4108.5,4752.3 4062.1,4752.3 4052.1,4762.3 U15.28@4052.1,4772.3 ; 3986,4929.5 4076,4929.5 4086,4919.5 ; U15.28@4052.1,4772.3 4052.1,4792.3 4042.1,4802.3 4042.1,4812.3 4057.8,4828.1 U15.3@4067.7,4828.1 U15.4@4067.7,4847.8 4077.7,4847.8 4097.7,4867.8 4097.7,4887.8 4086,4899.5 4086,4919.5
  Top Layer w9.9: U7.8@4358.6,5678.6 4363.6,5683.6 4525.8,5683.6 4615.8,5773.6 L2.2@4684.1,5773.6 ; U6.8@4573.1,4462.9 4592.3,4462.9 4672.3,4382.9 4672.3,4346.6 U10.6@4676.3,4342.6 4700.4,4342.6 4728.8,4314.2 ; U10.10@4728.8,4300.4 4728.8,4314.2 ; U10.1@4741.9,4322.9 4733.2,4314.2 4728.8,4314.2 ; C30.1@4931.3,4824 4960.6,4853.4 4960.6,4942.3 ; 5030.6,5082.3 5030.6,5092.3 5120.6,5182.3 5120.6,4978 5130.6,4968 5160.6,4968 5170.6,4978 5170.6,5008 5177.6,5015 C8.1@5177.6,5121 ; U13.5@5084.7,4892.8 U13.6@5084.7,4873.1 5077.3,4873.1 5069.9,4865.7 5069.9,4828.5 5079.9,4818.5 5129.9,4818.5 5148.6,4837.3 U13.10@5148.6,4848.5
  Top Layer w10: U9.6@4188.5,4626 4268.9,4706.4 C29.1@4444.1,4706.4 4514.5,4636 C27.1@4621.2,4636 4635.6,4621.5 4656.2,4621.5 ; U6.8@4573.1,4462.9 4681.7,4571.5 4686.2,4571.5 C32.1@4686.1,4581.5 ; L2.2@4684.1,5773.6 4782.4,5773.6 4812.4,5803.6 5115.5,5803.6 C31.1@5146.5,5834.5 ; C26.1@4776.2,4561.5 4696.2,4561.5 4656.2,4601.5 4656.2,4621.5 ; C30.1@4931.3,4824 4891.3,4824 4791.3,4724 4791.3,4706.6 C33.1@4789.1,4704.5 4779.1,4704.5 4716.2,4641.5 4676.2,4641.5 4656.2,4621.5 ; 4971.9,4292.9 5021.2,4292.9 R39.2@5119.1,4194.9 R6.2@5184.1,4194.9 5304.1,4194.9 5402.1,4096.9 U12.18@5419.1,4096.9 5419.1,3940.6 5579.1,3780.6 5627.5,3780.6 5667.5,3740.6 5667.5,3720.6 U12.6@5669.1,3719 5669.1,3682.6 5579.1,3592.6 5579.1,3582.6 5549.1,3552.6 5519.1,3552.6 5449.1,3482.6 5319.1,3482.6 5283.8,3517.9 5203.8,3517.9 5177.6,3544.2 C16.1@5177.6,3547.9 ; 5051.9,4402.9 5081.9,4402.9 R36.2@5114.9,4369.9 ; U11.3@5058.4,4472.8 U11.2@5089.9,4472.8 U11.7@5089.9,4583.1 ; R17.2@5095.5,5231.4 5120.6,5206.4 5120.6,5182.3 ; R36.2@5119.3,4369.9 R36.2@5114.9,4369.9 ; 5177.6,5085 v1(5197.6,5085) ; R38.2@5184.2,4369.9 R36.2@5114.9,4369.9 ; C28.1@5401.5,5879.6 5401.5,5887.3 5417.6,5903.5 5687.6,5903.5 5807.6,5783.5 5807.6,5225 5727.6,5145 5567.6,5145 v1(5557.6,5135) 5557.6,5045.8 U2.1@5552.8,5041 5642.8,4951 5642.8,4734.1 5705.6,4671.3 U17.1@5715.6,4671.3 5715.6,4516.8 R2.1@5797.2,4435.3 ; 5717.6,5873.5 5717.6,6011.4 H1.13@5759.1,6052.9 ; U31.3@5759.1,5667.9 5763.6,5663.5 5807.6,5663.5 ; 5807.6,5603.5 5847.6,5643.5 6023.6,5643.5 U20.3@6069.1,5597.9
  Inner1 w7.8: v1(4540.9,5033.6) 4570.9,5063.6 4570.9,5113.6 4710.9,5253.6 4760.9,5253.6 4800.9,5293.6 4800.9,5343.6 v1(4830.9,5373.6)
  Inner1 w10: v1(5197.6,5085) 5377.6,5265 5417.6,5265 5547.6,5135 v1(5557.6,5135)
  Inner2 w8.1: v1(3741.2,6099.1) 3771.2,6129.1 v1(3791.2,6129.1) ; v1(4188.6,5784.5) v1(4188.6,5914.5)
$1N340: U3.2 U3.3 U3.8 U3.9 USBC1.A4B9 | length 2986.7
  Top Layer w7.1: USBC1.A4B9@4798.6,6215.5 4798.6,6174.2 v1(4811.6,6161.2) ; U3.2@5325.9,4221.2 U3.3@5341.6,4221.2 5341.6,4256.5 v1(5351.6,4266.5) ; v1(5381.6,4161.2) 5471.6,4161.2 5491.6,4181.2 5491.6,4211.2 5466.6,4236.1 5456.6,4236.1 5441.6,4221.2 U3.8@5420.4,4221.2 ; U3.9@5446,4227.1 5451.6,4231.2
  Inner2 w7.1: v1(4811.6,6161.2) 4901.6,6071.2 4901.6,6051.2 4941.6,6011.2 4971.6,6011.2 5321.6,5661.2 5321.6,5381.2 5451.6,5251.2 5451.6,4851.2 5401.6,4801.2 5401.6,4381.2 5438.6,4344.1 5438.6,4208.2 5391.6,4161.2 v1(5381.6,4161.2)
  Bottom Layer w7.1: v1(5351.6,4266.5) 5351.6,4251.2 5301.6,4201.2 5291.6,4201.2 5271.6,4181.2 5271.6,4161.2 5291.6,4141.2 5301.6,4141.2 5321.6,4161.2 v1(5381.6,4161.2)
$1N342: U1.49 U12.8 | length 2171.2
  Top Layer w7.8: U1.49@4697.7,5336.1 4697.7,5313.1 v1(4707.7,5303.1) ; v1(5637.7,3873.1) 5769.1,3741.7 U12.8@5769.1,3719
  Inner2 w7.8: v1(4707.7,5303.1) 4727.7,5323.1 4777.7,5323.1 5077.7,5023.1 5147.7,5023.1 5277.7,4893.1 5277.7,4393.1 5327.7,4343.1 5327.7,4183.1 v1(5637.7,3873.1)
$1N343: R11.1 U12.10 | length 863.8
  Top Layer w10: R11.1@5177.1,3687.9 5177.1,3677.3 5196.5,3657.9 5236.5,3657.9 v1(5246.5,3667.9) ; v1(5659.1,3900.6) 5819.1,4060.6 U12.10@5819.1,4096.9
  Bottom Layer w10: v1(5246.5,3667.9) 5269.1,3690.6 5369.1,3690.6 5579.1,3900.6 v1(5659.1,3900.6)
$1N345: Q1.1 R11.2 R14.1 | length 423.6
  Top Layer w10: v1(5171.4,3788.1) 5171.4,3817.3 R14.1@5172.1,3817.9 ; R11.2@5211.1,3687.9 5221.3,3698.1 5251.4,3698.1 5396.1,3553.4 Q1.1@5396.1,3528.1
  Inner2 w10: v1(5171.4,3788.1) 5241.4,3718.1 v1(5241.4,3698.1)
$1N347: Q1.3 R16.1 U21.2 | length 788.1
  Top Layer w10: R16.1@5072.1,3815.3 5042.7,3785.9 5042.7,3745.5 5052.7,3735.5 5082.7,3735.5 5182.7,3635.5 5247.4,3635.5 Q1.3@5317.4,3565.5 ; v1(5112.7,3685.5) 5122.7,3695.5
  Inner2 w10: U21.2@4897,3488.3 4992.9,3488.3 5112.7,3608.1 v1(5112.7,3685.5)
$1N348: D2.1 R15.1 R16.2 U12.12 | length 1396.8
  Top Layer w10: D2.1@5079.7,3382.9 5116.7,3419.9 5116.7,3572.9 5156.7,3612.9 ; R16.2@5106.2,3815.3 5111.4,3820.6 5119.1,3820.6 ; v1(5139.1,3820.6) 5119.1,3820.6 ; R15.1@5177.1,3612.9 5156.7,3612.9 ; v1(5509.1,3890.6) 5529.1,3890.6 5719.1,4080.6 U12.12@5719.1,4096.9 ; 5119.1,3820.6 5099.1,3840.6 5059.1,3840.6 5019.1,3800.6 5019.1,3740.6 5099.1,3660.6 5109.1,3660.6 5156.7,3612.9
  Inner2 w10: v1(5139.1,3820.6) 5439.1,3820.6 v1(5509.1,3890.6)
$1N349: D1.1 R18.2 R19.1 U12.13 | length 1352.7
  Top Layer w10: v1(5085.1,3616.9) 5085.1,3483.3 D1.1@5084.7,3482.9 5044.7,3442.9 5044.7,3357.9 5054.7,3347.9 5104.7,3347.9 5184.7,3427.9 R19.1@5257.1,3427.9 ; R18.2@5211.1,3752.9 5225.1,3766.9 v1(5235.1,3766.9) ; v1(5479.1,3916.9) 5509.1,3916.9 5669.1,4076.9 U12.13@5669.1,4096.9
  Inner1 w10: v1(5085.1,3616.9) v1(5235.1,3766.9)
  Bottom Layer w10: v1(5235.1,3766.9) 5235.1,3771.9 5240.1,3776.9 5339.1,3776.9 v1(5479.1,3916.9)
$1N350: R13.1 U12.11 | length 890.3
  Top Layer w10: R13.1@5072.1,3757.9 5072.1,3763.5 5089.1,3780.6 5129.1,3780.6 5139.1,3770.6 v1(5139.1,3760.6) ; v1(5559.1,3840.6) 5769.1,4050.6 U12.11@5769.1,4096.9
  Inner1 w10: v1(5139.1,3760.6) 5189.1,3760.6 5269.1,3840.6 v1(5559.1,3840.6)
$1N351: Q2.1 R13.2 R20.1 | length 691.2
  Top Layer w10: R13.2@5106.1,3757.9 5133.5,3730.5 v1(5148.8,3730.5) ; v1(5508.8,3500.5) 5528.8,3520.5 Q2.1@5543.5,3520.5 5544.7,3520.5 R20.1@5642.1,3617.9
  Inner2 w10: v1(5148.8,3730.5) 5378.8,3500.5 v1(5508.8,3500.5)
$1N352: Q2.3 R18.1 U33.2 | length 1344.5
  Top Layer w10: R18.1@5177.1,3752.9 5177.1,3742.9 5197.1,3722.9 5235,3722.9 v1(5260,3747.9) ; v1(5440,3607.9) 5464.7,3583.2 Q2.3@5464.7,3557.9
  Inner1 w10: U33.2@4427.4,3493.9 4487.4,3553.9 4954.9,3553.9 ; 4958,3553.8 5055.9,3553.8 5250,3747.9 v1(5260,3747.9) 5300,3747.9 v1(5440,3607.9)
$1N353: R38.1 U1.13 U3.15 U8.4 U9.4 U12.2 U18.30 | length 5026.6
  Top Layer w7.1: v1(5426.2,3897.3) 5469.1,3854.4 U12.2@5469.1,3719 ; U3.15@5447.9,4337.3 5466.2,4337.3 5476.2,4347.3 v1(5476.2,4377.3)
  Top Layer w7.8: U9.4@4168.8,4459.9 4168.8,4369.9 4248.8,4289.9 4392.7,4289.9 4412.7,4309.8 4412.7,4356.4 4429.6,4339.5 cw(c4417.6,4327.5) v1@4434.6,4327.5 ; v1(5048.8,4329.9) 5068.8,4309.9 5158.2,4309.9 R38.1@5184.2,4335.8
  Top Layer w8.1: v1(3738.8,5856.7) 3765.9,5856.7 U18.30@3767.3,5855.3
  Top Layer w10: U8.4@3859.3,5092.6 3892.9,5092.6 3908.8,5076.7 v1(3908.8,5006.7) ; U9.4@4168.8,4459.9 4168.8,4506.7 v1(4178.8,4516.7) ; U1.13@4713.9,4940.9 4713.9,4936.6 ccw(c4724.9,4936.6) 4714.49,4933.04 ; v1@4714.5,4882.9 4714.5,4933.1
  Inner1 w7.1: v1(5048.8,4329.9) 5241.4,4137.3 5396.2,4137.3 ; v1(5426.2,3897.3) 5396.2,3927.3 5396.2,4137.3 ; v1(5476.2,4377.3) 5486.2,4367.3 5486.2,4197.3 5426.2,4137.3 5396.2,4137.3
  Inner1 w7.8: v1@4436.4,4324.1 4453.8,4324.1 ; 4454.3,4324.4 4528.8,4249.9 4958.8,4249.9 5038.8,4329.9 v1(5048.8,4329.9)
  Inner1 w8.1: v1(3738.8,5856.7) 3728.8,5846.7 3728.8,5186.7 v1(3908.8,5006.7)
  Inner1 w10: v1(3908.8,5006.7) 3878.8,4976.7 3878.8,4816.7 v1(4178.8,4516.7) ; v1@4435.8,4323.5 4436.4,4324.1 4543.7,4431.5 ccw(c4473,4502.2) 4573,4502.2 v1@4573,4560.4
  Inner2 w10: v1@4581.1,4759.9 4697.8,4876.6 ; 4697.86,4876.54 cw(c4713.2,4861.2) v1@4713.2,4882.9
  Bottom Layer w10: v1@4577.9,4562.8 4577.9,4754.6 cw(c4587,4754.6) v1@4580.57,4761.03
  other v1: 4435.6,4324.5 4573.6,4562.2 4581.8,4760.9 4714.4,4882.9
$1N356: C11.1 C12.1 C13.1 C14.1 L1.2 U1.10 U1.32 U1.51 U1.59 U1.65 | length 3934.6
  Top Layer w7.8: L1.2@4349.1,5928.1 4394.7,5928.1 4454.7,5868.1 4454.7,5758.1 v1(4404.7,5708.1) ; v1(4414.7,5608.1) 4404.7,5598.1 4404.7,5268.1 4443.3,5229.5 U1.65@4480.9,5229.5 ; 4434.7,5238.1 4444.7,5228.1 4534.7,5228.1 4564.7,5198.1 4564.7,5188.1 4594.7,5158.1 4594.7,5068.1 4664.7,4998.1 4664.7,4968.1 ; 4454.7,5778.1 4534.7,5778.1 4634.7,5878.1 4854.7,5878.1 4893.4,5839.4 C14.1@5051.5,5839.4 ; U1.59@4540.2,5336.1 4540.2,5472.6 v1(4580.2,5512.6) ; 4540.2,5442.6 4610.2,5442.6 4666.2,5386.6 U1.51@4666.2,5336.1 ; v1(4628.9,5028.1) 4638.9,5028.1 4664.7,5002.2 4664.7,4968.1 ; U1.10@4666.2,4949.7 4664.7,4951.2 4664.7,4968.1 ; U1.32@4867.3,5166.5 4920.4,5166.5 5027.3,5059.6 v1(5027.3,5019.6)
  Top Layer w10: 5023.4,5839.4 5023.4,5919.4 5033.4,5929.4 5103.4,5929.4 5133.4,5899.4 C11.1@5143.4,5899.4 ; C11.1@5146.5,5899.5 C11.1@5143.4,5899.4 ; v1(5193.4,5929.4) 5173.4,5929.4 C11.1@5143.4,5899.4 ; v1(5306.5,5842.6) C13.1@5306.5,5819.5 5306.5,5814.6 5326.5,5794.6 5381.5,5794.6 C12.1@5401.5,5814.6
  Inner1 w7.8: v1(4404.7,5708.1) 4404.7,5688.1 v1(4580.2,5512.6)
  Inner2 w7.8: v1(4404.7,5708.1) 4404.7,5618.1 v1(4414.7,5608.1)
  Inner2 w10: v1(5193.4,5929.4) 5219.6,5929.4 v1(5306.5,5842.6)
  Bottom Layer w7.8: v1(4628.9,5028.1) 4638.9,5018.1 4658.9,5018.1 4698.9,5058.1 4858.9,5058.1 4877.3,5039.6 5007.3,5039.6 v1(5027.3,5019.6)
pads on no net: CARD1.3 CARD1.4 CARD1.6 CARD1.8 U2.8 U4.5 U5.5 U10.7 U12.7 U12.14 U12.15 U12.16 U12.17 U13.7 U13.8 U14.6 U14.9 U14.10 U14.12 U14.13 U15.1 U15.5 U15.6 U15.7 U15.8 U15.12 U15.13 U15.21 U15.22 U15.23 U15.24 U15.26 U15.27 U16.2 U16.4 U18.4 U18.5 U18.8 U18.9 U18.10 U18.11 U18.12 U18.13 U18.23 U18.26 U18.27 U18.28 U18.29 U18.39 U18.40 U18.41 U18.42 U18.43 U18.44 U18.45 U18.46 U18.47 U18.48 U18.49 U18.50 U18.51 U18.52 U18.60 U18.61 U18.62 U18.63 U18.64 U18.65 U18.66 U18.67 U18.68 U18.69 U18.70 U18.72 U22.2 U22.4 USBC1.1 USBC1.2 USBC1.3 USBC1.4 USBC1.A8 USBC1.B4A9 USBC1.B6 USBC1.B7 USBC1.B8 X2.1 X2.3

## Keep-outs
Board Outline Layer:
  lines w10: 3000.1,4792 3000.9,4753.9 3002.5,4715.9 3004.9,4677.9 3008.1,4640 3012.1,4602.2 3016.9,4564.4 3022.4,4526.8 3028.8,4489.3 3036,4451.9 3043.9,4414.7 3052.6,4377.6 3062.1,4340.8 3072.4,4304.1 3083.4,4267.7 3095.2,4231.5 3107.8,4195.6 3121.1,4159.9 3135.1,4124.6 3149.9,4089.5 3165.5,4054.8 3181.7,4020.4 3198.7,3986.3 3216.4,3952.6 3234.8,3919.3 3253.8,3886.4 3273.6,3853.8 3294.1,3821.7 3315.2,3790.1 3337,3758.9 3359.4,3728.1 3382.5,3697.9 3406.2,3668.1 3430.5,3638.8 3455.5,3610.1 3481,3581.9 3507.1,3554.2 3533.8,3527.1 3561.1,3500.5 3588.9,3474.5 3617.2,3449.2 3646.1,3424.4 3675.5,3400.2 3705.4,3376.7 3735.8,3353.7 3766.6,3331.5 3798,3309.9 3829.7,3288.9 3861.9,3268.6 3894.5,3249 3927.6,3230.1 3961,3211.9 3994.8,3194.4 4028.9,3177.6 4063.4,3161.5 4098.2,3146.2 4133.4,3131.6 4168.8,3117.7 4204.5,3104.6 4240.5,3092.2 4276.8,3080.6 4313.3,3069.7 4350,3059.7 4386.9,3050.4 4424,3041.8 4461.2,3034.1 4498.6,3027.1 4536.2,3021 4573.9,3015.6 4611.6,3011 4649.5,3007.2 4687.4,3004.2 4725.4,3002 4763.5,3000.6 4801.5,3000 4839.6,3000.2 4877.6,3001.2 4915.6,3003 4953.6,3005.6 4991.5,3009 5029.3,3013.2 5067,3018.2 5104.7,3024 5142.1,3030.5 5179.5,3037.9 5216.7,3046 5253.7,3054.9 5290.5,3064.6 5327.1,3075.1 5363.4,3086.3 5399.5,3098.3 5435.4,3111 5471,3124.5 5506.3,3138.8 5541.3,3153.7 5575.9,3169.5 5610.2,3185.9 5644.2,3203 5677.8,3220.9 5711,3239.5 5743.9,3258.7 5776.3,3278.7 5808.3,3299.3 5839.8,3320.6 5870.9,3342.5 5901.5,3365.1 5931.7,3388.4 5961.3,3412.2 5990.4,3436.7 6019.1,3461.8 6047.1,3487.5 6074.7,3513.7 6101.7,3540.6 6128.1,3568 6153.9,3595.9 6179.1,3624.4 6203.8,3653.4 6227.8,3682.9 6251.2,3713 6273.9,3743.5 6296,3774.4 6317.5,3805.9 6338.3,3837.7 6358.4,3870 6377.8,3902.8 6396.6,3935.9 6414.6,3969.4 6431.9,4003.3 6448.6,4037.5 6464.4,4072.1 6479.6,4107 6494,4142.2 6507.7,4177.7 6520.6,4213.5 6532.8,4249.6 6544.2,4285.9 6554.9,4322.4 6564.8,4359.2 6573.9,4396.1 6582.2,4433.2 6589.8,4470.6 6596.5,4508 6602.5,4545.6 6607.7,4583.3 6612.1,4621.1 6615.7,4659 6618.4,4696.9 6620.4,4734.9 6621.6,4773 6622,4811 6621.6,4849.1 6620.4,4887.1 6618.4,4925.1 6615.7,4963.1 6612.1,5001 6607.7,5038.8 6602.5,5076.5 6596.5,5114 6589.8,5151.5 6582.2,5188.8 6573.9,5225.9 6564.8,5262.9 6554.9,5299.6 6544.2,5336.2 6532.8,5372.5 6520.6,5408.5 6507.7,5444.3 6494,5479.8 6479.6,5515 6464.4,5550 6448.6,5584.5 6431.9,5618.8 6414.6,5652.6 6396.6,5686.2 6377.8,5719.3 6358.4,5752 6338.3,5784.3 6317.5,5816.2 6296,5847.6 6273.9,5878.6 6251.2,5909.1 6227.8,5939.1 6203.8,5968.6 6179.1,5997.6 6153.9,6026.1 6128.1,6054.1 6101.7,6081.5 6074.7,6108.3 6047.1,6134.6 6019.1,6160.3 5990.4,6185.4 5961.3,6209.8 5931.7,6233.7 5901.5,6256.9 5870.9,6279.5 5839.8,6301.5 5808.3,6322.8 5776.3,6343.4 5743.9,6363.3 5711,6382.6 5677.8,6401.1 5644.2,6419 5610.2,6436.2 5575.9,6452.6 5541.3,6468.3 5506.3,6483.3 5471,6497.5 5435.4,6511 5399.5,6523.8 5363.4,6535.7 5327.1,6547 5290.5,6557.4 5253.7,6567.1 5216.7,6576 5179.5,6584.2 5142.1,6591.5 5104.7,6598.1 5067,6603.9 5029.3,6608.8 4991.5,6613 4953.6,6616.4 4915.6,6619 4877.6,6620.8 4839.6,6621.8 4801.5,6622 4763.5,6621.4 4725.4,6620 4687.4,6617.8 4649.5,6614.8 4611.6,6611 4573.9,6606.4 4536.2,6601.1 4498.6,6594.9 4461.2,6587.9 4424,6580.2 4386.9,6571.7 4350,6562.4 4313.3,6552.3 4276.8,6541.5 4240.5,6529.8 4204.5,6517.5 4168.8,6504.4 4133.4,6490.5 4098.2,6475.9 4063.4,6460.5 4028.9,6444.5 3994.8,6427.7 3961,6410.2 3927.6,6391.9 3894.5,6373 3861.9,6353.4 3829.7,6333.1 3798,6312.2 3766.6,6290.6 3735.8,6268.3 3705.4,6245.4 3675.5,6221.8 3646.1,6197.7 3617.2,6172.9 3588.9,6147.5 3561.1,6121.5 3533.8,6095 3507.1,6067.8 3481,6040.2 3455.5,6012 3430.5,5983.2 3406.2,5953.9 3382.5,5924.2 3359.4,5893.9 3337,5863.2 3315.2,5832 3294.1,5800.3 3273.6,5768.2 3253.8,5735.7 3234.8,5702.8 3216.4,5669.5 3198.7,5635.8 3181.7,5601.7 3165.5,5567.3 3149.9,5532.5 3135.1,5497.5 3121.1,5462.1 3107.8,5426.5 3095.2,5390.5 3083.4,5354.3 3072.4,5317.9 3062.1,5281.3 3052.6,5244.4 3043.9,5207.4 3036,5170.2 3028.8,5132.8 3022.4,5095.3 3016.9,5057.6 3012.1,5019.9 3008.1,4982 3004.9,4944.1 3002.5,4906.1 3000.9,4868.1 3000.1,4830.1 3000.1,4792

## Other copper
Top Layer:
  text "Brake Header" at 3169.1,5097.9 h39.4
  text "Ejection Ports" at 3879.1,3367.9 h39.4
  text "WYVERN-E" at 4456.9,3106.6 h120
Bottom Layer:
  text "TVC Header" at 5231.7,3887.9 h39.4
  text "Fin Header" at 3614.1,3797.9 h39.4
